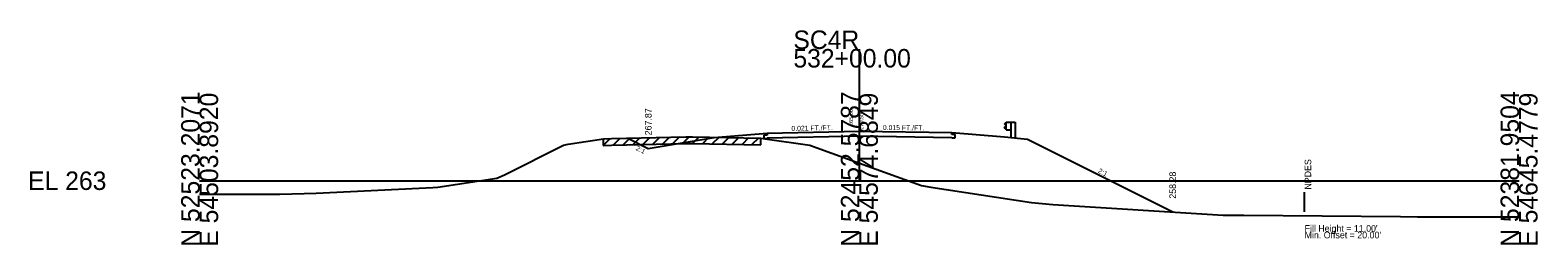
# Model space of a CAD drawing. Extents: x 7498 to 13027, y 90095 to 109625.
# Drawn here: x 9498.3 to 9726.8, y 102095.5 to 102127.9 of the extents above; entities that cross this region are included whole.
import ezdxf

# ---------------------------------------------------------------- set-up
doc = ezdxf.new("R2010")
doc.units = 0
for name, color, linetype in [('Level 10', 7, 'Continuous'), ('Level 11', 7, 'Continuous'), ('Level 12', 7, 'Continuous'), ('Level 24', 7, 'Continuous'), ('Level 32', 7, 'Continuous'), ('Level 33', 7, 'Continuous'), ('Level 50', 7, 'Continuous'), ('Level 55', 7, 'Continuous'), ('Level 59', 7, 'Continuous'), ('Level 6', 7, 'Continuous'), ('Level 60', 7, 'Continuous'), ('Level 61', 7, 'Continuous'), ('Level 63', 7, 'Continuous'), ('Level 7', 7, 'Continuous')]:
    doc.layers.add(name, color=color, linetype=linetype)

msp = doc.modelspace()

# ---------------------------------------------------------------- linework, layer by layer
at = {"layer": 'Level 11'}
for p, q in [((9609.99, 102112.07), (9609.49, 102112.05)), ((9609.49, 102112.05), (9609.49, 102111.57)), ((9609.99, 102112.37), (9609.99, 102112.07)), ((9637.99, 102112.15), (9637.99, 102112.45)), ((9638.49, 102112.14), (9637.99, 102112.15)), ((9638.49, 102111.66), (9638.49, 102112.14)), ((9609.49, 102111.57), (9609.99, 102111.59)), ((9637.99, 102111.67), (9638.49, 102111.66))]:
    msp.add_line(p, q, dxfattribs=at)
at = {"layer": 'Level 12'}
for p, q in [((9623.99, 102111.88), (9609.99, 102111.59)), ((9637.99, 102111.67), (9623.99, 102111.88))]:
    msp.add_line(p, q, dxfattribs=at)
at = {"layer": 'Level 24'}
for p, q in [((9646.26, 102112.87), (9646.26, 102114.04)), ((9646.26, 102114.04), (9646.93, 102114.04)), ((9646.93, 102114.04), (9646.93, 102111.69)), ((9646.93, 102114.04), (9647.6, 102114.04)), ((9647.6, 102114.04), (9647.6, 102111.63)), ((9646.26, 102113.96), (9645.99, 102113.76)), ((9645.99, 102113.76), (9645.99, 102113.71)), ((9645.99, 102113.71), (9646.26, 102113.51)), ((9645.99, 102113.19), (9646.26, 102113.39)), ((9645.99, 102113.14), (9645.99, 102113.19)), ((9646.26, 102112.94), (9645.99, 102113.14)), ((9646.26, 102112.87), (9646.93, 102112.87))]:
    msp.add_line(p, q, dxfattribs=at)
at = {"layer": 'Level 55'}
msp.add_line((9691.48, 102100.44), (9691.48, 102103.44), dxfattribs=at)
at = {"layer": 'Level 59'}
for p, q in [((9609.99, 102112.37), (9623.99, 102112.66)), ((9623.99, 102112.66), (9637.99, 102112.45))]:
    msp.add_line(p, q, dxfattribs=at)
at = {"layer": 'Level 6'}
for p, q in [((9601.99, 102111.7), (9609.99, 102112.37)), ((9637.99, 102112.45), (9645.99, 102111.79)), ((9645.99, 102111.79), (9649.49, 102111.44))]:
    msp.add_line(p, q, dxfattribs=at)
at = {"layer": 'Level 60'}
for p, q in [((9586.41, 102111.53), (9597.68, 102111.8)), ((9597.68, 102111.8), (9598.7, 102111.79)), ((9598.7, 102111.79), (9609.05, 102111.6)), ((9570.18, 102106.05), (9579.16, 102110.53)), ((9579.16, 102110.53), (9579.83, 102110.7)), ((9579.83, 102110.7), (9585.2, 102111.5)), ((9585.2, 102111.5), (9586.41, 102111.53)), ((9609.05, 102111.6), (9609.7, 102111.52)), ((9609.7, 102111.52), (9616.48, 102110.53)), ((9616.48, 102110.53), (9617.98, 102109.98)), ((9617.98, 102109.98), (9623.99, 102107.82)), ((9623.99, 102107.82), (9633.39, 102104.43)), ((9560.09, 102104.2), (9569.03, 102105.54)), ((9569.03, 102105.54), (9570.18, 102106.05)), ((9523.99, 102103.11), (9536.12, 102103.11)), ((9536.12, 102103.11), (9541.66, 102103.27)), ((9541.66, 102103.27), (9559.33, 102104.15)), ((9559.33, 102104.15), (9560.09, 102104.2)), ((9633.39, 102104.43), (9634.84, 102104.2)), ((9634.84, 102104.2), (9650.08, 102101.86)), ((9650.08, 102101.86), (9653.3, 102101.58)), ((9653.3, 102101.58), (9679.15, 102099.96)), ((9679.15, 102099.96), (9682.29, 102099.93)), ((9682.29, 102099.93), (9706.01, 102099.74)), ((9706.01, 102099.74), (9708.57, 102099.68)), ((9708.57, 102099.68), (9723.99, 102099.67))]:
    msp.add_line(p, q, dxfattribs=at)
at = {"layer": 'Level 61'}
for p, q in [((9595.21, 102111.74), (9594.18, 102110.72)), ((9596.71, 102111.78), (9595.68, 102110.75)), ((9598.19, 102111.79), (9597.19, 102110.79)), ((9599.67, 102111.77), (9598.69, 102110.79)), ((9601.18, 102111.74), (9600.19, 102110.76)), ((9586.2, 102111.53), (9585.17, 102110.49)), ((9585.17, 102111.49), (9585.17, 102110.49)), ((9585.17, 102110.49), (9585.2, 102110.5)), ((9585.2, 102110.5), (9586.41, 102110.53)), ((9586.41, 102110.53), (9597.68, 102110.8)), ((9587.7, 102111.56), (9586.67, 102110.54)), ((9589.2, 102111.6), (9588.17, 102110.57)), ((9590.7, 102111.63), (9589.67, 102110.61)), ((9592.2, 102111.67), (9591.18, 102110.65)), ((9593.71, 102111.71), (9592.68, 102110.68)), ((9597.68, 102110.8), (9598.7, 102110.79)), ((9598.7, 102110.79), (9609.05, 102110.6)), ((9602.68, 102111.72), (9601.69, 102110.73)), ((9604.18, 102111.69), (9603.2, 102110.71)), ((9605.68, 102111.66), (9604.7, 102110.68)), ((9607.19, 102111.64), (9606.2, 102110.65)), ((9608.69, 102111.61), (9607.7, 102110.63)), ((9609.05, 102110.6), (9609.07, 102110.6)), ((9609.07, 102110.6), (9609.07, 102111.6))]:
    msp.add_line(p, q, dxfattribs=at)
at = {"layer": 'Level 63'}
for p, q in [((9623.99, 102105.16), (9623.99, 102125.09)), ((9523.99, 102105.16), (9623.99, 102105.16)), ((9623.99, 102105.16), (9723.99, 102105.16))]:
    msp.add_line(p, q, dxfattribs=at)
at = {"layer": 'Level 7'}
for p, q in [((9588.88, 102111.59), (9591.99, 102110.03)), ((9591.99, 102110.03), (9601.99, 102111.7)), ((9649.49, 102111.44), (9671.48, 102100.44))]:
    msp.add_line(p, q, dxfattribs=at)

# ---------------------------------------------------------------- texts
at = {"layer": 'Level 10'}
msp.add_text('265.66', height=0.6, rotation=90, dxfattribs=at).set_placement((9623.02, 102113.45))
at = {"layer": 'Level 32'}
for s, rotation, p in [('0.021 FT./FT.', 1.1916, (9613.7, 102112.69)), ('0.015 FT./FT.', 359.1642, (9627.55, 102112.85)), ('2:1', 333.435, (9590.04, 102109.82)), ('2:1', 333.435, (9660.09, 102106.41))]:
    msp.add_text(s, height=0.75, rotation=rotation, dxfattribs=at).set_placement(p)
at = {"layer": 'Level 33'}
for s, p in [('267.87', (9592.49, 102112.03)), ('258.28', (9671.98, 102102.44))]:
    msp.add_text(s, height=1, rotation=90, dxfattribs=at).set_placement(p)
at = {"layer": 'Level 50'}
msp.add_text(' NPDES', height=1, rotation=90, dxfattribs=at).set_placement((9692.48, 102103.44))
for s, p in [("Fill Height = 11.00' ", (9691.48, 102097.44)), ("Min. Offset = 20.00' ", (9691.48, 102096.44))]:
    msp.add_text(s, height=1, dxfattribs=at).set_placement(p)
at = {"layer": 'Level 59'}
msp.add_text(' 270.50', height=0.6, rotation=90, dxfattribs=at).set_placement((9624.59, 102112.66))
at = {"layer": 'Level 63'}
for s, p in [('SC4R', (9613.99, 102125.09)), ('532+00.00', (9613.99, 102122.29)), ('EL 263', (9497.99, 102103.76))]:
    msp.add_text(s, height=2.8, dxfattribs=at).set_placement(p)
for s, p in [('N 52523.2071', (9523.99, 102095.16)), ('E 54503.8920', (9526.79, 102095.16)), ('N 52452.5787', (9623.99, 102095.16)), ('E 54574.6849', (9626.79, 102095.16)), ('N 52381.9504', (9723.99, 102095.16)), ('E 54645.4779', (9726.79, 102095.16))]:
    msp.add_text(s, height=2.8, rotation=90, dxfattribs=at).set_placement(p)

doc.saveas('drawing.dxf')
